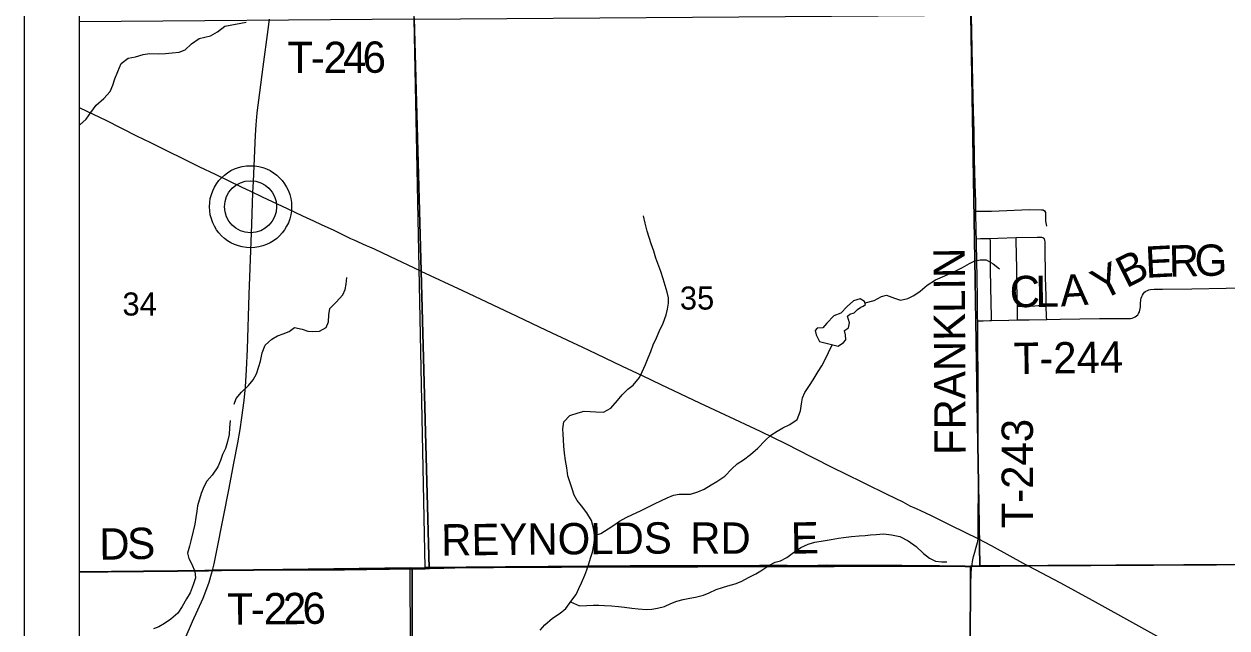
# Model space of a CAD drawing. Extents: x 0 to 70.2, y 0 to 31.4.
# Drawn here: x 2 to 4.18, y 18.211 to 19.306 of the extents above; entities that cross this region are included whole.
import ezdxf

# ---------------------------------------------------------------- set-up
doc = ezdxf.new("R2010")
doc.units = 0
for name, color, linetype in [('GM_X_County_Road', 7, 'Continuous'), ('GM_X_Minor_Lake', 7, 'Continuous'), ('GM_X_Minor_River', 7, 'Continuous'), ('GM_X_Section', 7, 'Continuous'), ('GM_X_Section_Text', 7, 'Continuous'), ('GM_X_State_Route', 7, 'Continuous'), ('GM_X_Township_Road', 7, 'Continuous'), ('GM_X_Township_Road_Text', 7, 'Continuous'), ('GM_X_Unincorporated', 7, 'Continuous'), ('GM_X_Unincorporated_Location', 7, 'Continuous'), ('SH_Cut_Line', 7, 'Continuous'), ('SH_Data', 7, 'Continuous')]:
    doc.layers.add(name, color=color, linetype=linetype)

msp = doc.modelspace()

# ---------------------------------------------------------------- linework, layer by layer
at = {"layer": 'GM_X_County_Road'}
for points in [[(3.7171, 18.3219), (3.7185, 18.3314), (3.7204, 18.3404), (3.7231, 18.35), (3.7241, 18.3535), (3.7279, 18.3656), (3.7285, 18.3683), (3.7289, 18.3723)], [(3.7167, 17.7404), (3.7171, 17.8383), (3.7174, 17.9202), (3.7173, 17.9902), (3.7166, 18.078), (3.7155, 18.164), (3.7152, 18.2197), (3.7156, 18.2754), (3.7156, 18.2911), (3.716, 18.3093), (3.7167, 18.3191), (3.7171, 18.3219)]]:
    msp.add_lwpolyline(points, dxfattribs=at)
at = {"layer": 'GM_X_Minor_Lake'}
for points in [[(3.4749, 18.7219), (3.4851, 18.7283), (3.4893, 18.7336), (3.4886, 18.7427), (3.4864, 18.7503), (3.494, 18.7552), (3.4955, 18.7643), (3.4918, 18.7761), (3.496, 18.7799), (3.5044, 18.7825), (3.5101, 18.7885), (3.5162, 18.7927), (3.5207, 18.7942), (3.5249, 18.7976), (3.523, 18.8029), (3.5151, 18.8075), (3.5029, 18.8041), (3.4915, 18.7939), (3.4797, 18.7815), (3.4675, 18.777), (3.4546, 18.7634), (3.4473, 18.7554), (3.4371, 18.7547), (3.4336, 18.7502), (3.4355, 18.7422), (3.4415, 18.7304)], [(3.4415, 18.7304), (3.4749, 18.7219)]]:
    msp.add_lwpolyline(points, dxfattribs=at)
at = {"layer": 'GM_X_Minor_River'}
for points in [[(2.1, 19.1227), (2.1005, 19.1228), (2.1124, 19.1333), (2.1209, 19.1458), (2.1309, 19.1589), (2.1443, 19.1709), (2.1558, 19.1837), (2.1609, 19.1951), (2.1644, 19.2064), (2.1699, 19.2196), (2.1758, 19.2344), (2.1884, 19.2441), (2.2017, 19.2462), (2.2158, 19.251), (2.2276, 19.2524), (2.2431, 19.2522), (2.2564, 19.2528), (2.2682, 19.2538), (2.2811, 19.2552), (2.2922, 19.2589), (2.3037, 19.2701), (2.3171, 19.2795), (2.3377, 19.2845), (2.3507, 19.292), (2.364, 19.3021)], [(2.364, 19.3021), (2.4024, 19.3094)], [(2.9351, 18.2067), (2.9435, 18.2166), (2.9576, 18.229), (2.9713, 18.2377), (2.9816, 18.2464), (2.9923, 18.2611), (3.0003, 18.2717), (3.0053, 18.2823), (3.0103, 18.2926), (3.0164, 18.3066), (3.0199, 18.3164), (3.0234, 18.3274), (3.0261, 18.3373), (3.0299, 18.3483), (3.0326, 18.3608), (3.0334, 18.3703), (3.0338, 18.3797), (3.0316, 18.3919), (3.0279, 18.4056), (3.02, 18.4197), (3.0102, 18.4322), (3.0023, 18.4421), (2.997, 18.4517), (2.9929, 18.4631), (2.9888, 18.4756), (2.9854, 18.4866), (2.9832, 18.5011), (2.981, 18.5144), (2.9795, 18.528), (2.9781, 18.5406), (2.9774, 18.552), (2.9767, 18.5622), (2.9763, 18.5717), (2.9783, 18.5846), (2.989, 18.596), (3.0038, 18.6012), (3.0152, 18.6038), (3.0258, 18.6034), (3.036, 18.6026), (3.0497, 18.6025), (3.0634, 18.6096), (3.0752, 18.6236), (3.0836, 18.6338), (3.0939, 18.6437), (3.1034, 18.6512), (3.1149, 18.6652), (3.1202, 18.6754), (3.126, 18.6887), (3.131, 18.7008), (3.136, 18.7125), (3.1398, 18.7243), (3.146, 18.7372), (3.151, 18.7485), (3.1579, 18.7633), (3.1636, 18.7784), (3.1659, 18.7887), (3.1675, 18.8001), (3.1676, 18.8096), (3.1653, 18.8198), (3.1616, 18.8316), (3.1579, 18.8438), (3.1537, 18.8571), (3.1481, 18.8715), (3.1448, 18.8814), (3.141, 18.894), (3.1365, 18.9073), (3.1328, 18.9187), (3.1291, 18.9305), (3.1257, 18.9449), (3.1227, 18.9582)], [(3.5238, 18.8006), (3.5401, 18.8047), (3.5534, 18.8119), (3.5629, 18.8141), (3.577, 18.8091), (3.5879, 18.8052), (3.6016, 18.8082), (3.6123, 18.8138), (3.6237, 18.8218), (3.6363, 18.8323), (3.6515, 18.8421), (3.664, 18.8478), (3.6792, 18.8541), (3.6895, 18.859), (3.7002, 18.8647), (3.7131, 18.8718), (3.723, 18.8763), (3.7325, 18.8786), (3.7431, 18.8785), (3.756, 18.8712), (3.7677, 18.8621)], [(2.3805, 18.6167), (2.3843, 18.627), (2.3942, 18.6387), (2.4064, 18.6504), (2.4152, 18.661), (2.421, 18.672), (2.4256, 18.6852), (2.4283, 18.6947), (2.4314, 18.7099), (2.4371, 18.7239), (2.4489, 18.7345), (2.4592, 18.7405), (2.4695, 18.7442), (2.4805, 18.7487), (2.49, 18.7555), (2.5041, 18.7528), (2.5139, 18.749), (2.5234, 18.7485), (2.5352, 18.7492), (2.5473, 18.7556), (2.5515, 18.7662), (2.552, 18.7788), (2.5543, 18.7901), (2.5658, 18.8018), (2.5776, 18.8147), (2.5818, 18.8245), (2.5837, 18.8344), (2.5849, 18.8462)], [(3.0338, 18.3784), (3.0452, 18.382), (3.0586, 18.3906), (3.0685, 18.3974), (3.0791, 18.4046), (3.0913, 18.4114), (3.1023, 18.4166), (3.1168, 18.4234), (3.1301, 18.4298), (3.1434, 18.4365), (3.154, 18.4414), (3.1654, 18.4471), (3.1765, 18.4519), (3.1871, 18.4538), (3.1966, 18.4534), (3.2076, 18.4537), (3.2209, 18.4578), (3.2323, 18.4623), (3.2449, 18.4702), (3.2555, 18.4766), (3.2696, 18.4864), (3.2822, 18.4992), (3.2921, 18.5083), (3.3035, 18.5155), (3.3165, 18.5257), (3.3294, 18.537), (3.3431, 18.551), (3.353, 18.5604), (3.3645, 18.5676), (3.3747, 18.574), (3.3873, 18.58), (3.4006, 18.589), (3.4068, 18.6046), (3.4087, 18.6174), (3.4107, 18.6281), (3.4145, 18.6379), (3.4233, 18.6508), (3.4298, 18.6606), (3.439, 18.6758), (3.4455, 18.6864), (3.4512, 18.6966), (3.4645, 18.7245)], [(2.3736, 18.5873), (2.3723, 18.5737), (2.3714, 18.5619), (2.3686, 18.549), (2.365, 18.5362), (2.3596, 18.5256), (2.3557, 18.5143), (2.351, 18.5029), (2.3406, 18.4878), (2.3313, 18.4769), (2.3255, 18.4671), (2.3208, 18.455), (2.3145, 18.4323), (2.3129, 18.4225), (2.3112, 18.4111), (2.3092, 18.3994), (2.3064, 18.3865), (2.302, 18.3691), (2.2996, 18.3592), (2.2961, 18.3467), (2.2986, 18.3368), (2.3042, 18.3265), (2.3094, 18.3131), (2.3108, 18.3021), (2.3065, 18.2893), (2.301, 18.2745), (2.2944, 18.264), (2.2867, 18.25), (2.2789, 18.2379), (2.2659, 18.2267), (2.2544, 18.2188), (2.2441, 18.2129), (2.2346, 18.2096)], [(2.9903, 18.2584), (3.0067, 18.2508), (3.02, 18.2515), (3.0317, 18.2522), (3.0412, 18.2522), (3.0518, 18.2514), (3.0643, 18.2509), (3.0772, 18.2497), (3.0882, 18.2485), (3.1011, 18.2469), (3.1129, 18.2454), (3.1277, 18.2445), (3.1375, 18.2452), (3.1478, 18.2467), (3.1603, 18.2501), (3.1721, 18.2553), (3.1831, 18.2594), (3.1942, 18.2628), (3.2063, 18.265), (3.2169, 18.2669), (3.2314, 18.2706), (3.2416, 18.2747), (3.2542, 18.2804), (3.2656, 18.2845), (3.2755, 18.2875), (3.2884, 18.2908), (3.2994, 18.2949), (3.3139, 18.3028), (3.3257, 18.3092), (3.3352, 18.3145), (3.3493, 18.3243), (3.3611, 18.3303), (3.3705, 18.3326), (3.3823, 18.3386), (3.3919, 18.3457), (3.4075, 18.3567), (3.4208, 18.3631), (3.4329, 18.3668), (3.4481, 18.369), (3.4622, 18.3712), (3.4755, 18.3738), (3.485, 18.3749), (3.4994, 18.3767), (3.513, 18.3778), (3.5241, 18.3785), (3.5335, 18.3796), (3.5438, 18.3807), (3.5575, 18.3814), (3.5715, 18.3798), (3.5867, 18.3767), (3.6018, 18.369), (3.6165, 18.3587), (3.6298, 18.3461), (3.6407, 18.3377), (3.6517, 18.3323), (3.6627, 18.3311), (3.6722, 18.3311)]]:
    msp.add_lwpolyline(points, dxfattribs=at)
at = {"layer": 'GM_X_Section'}
for points in [[(3.7154, 19.3219), (4.7288, 19.3363), (4.7368, 18.3286), (4.7171, 18.3286), (3.7317, 18.3233)], [(2.7066, 19.3148), (3.7154, 19.3219), (3.7317, 18.3233), (3.715, 18.323), (2.7267, 18.3203)], [(3.715, 18.323), (3.7116, 17.3342), (2.7039, 17.3191), (2.6994, 18.3199), (2.7267, 18.3203)], [(4.7171, 18.3286), (4.7109, 17.3315), (3.7116, 17.3342), (3.715, 18.323), (3.7317, 18.3233)]]:
    msp.add_lwpolyline(points, close=True, dxfattribs=at)
at = {"layer": 'GM_X_Section_Text'}
for points in [[(2.1, 20.9), (2.1, 18.3126), (2.2164, 18.3137), (2.2784, 18.3145), (2.3277, 18.3152), (2.3343, 18.3153), (2.3412, 18.3156), (2.3574, 18.3156), (2.4158, 18.3166), (2.4655, 18.3166), (2.5245, 18.3166), (2.5804, 18.317), (2.6618, 18.318), (2.7031, 18.3186), (2.7265, 18.319), (2.7342, 18.3192), (2.7194, 18.8581), (2.7067, 19.3173), (2.6915, 19.8217), (2.6758, 20.3443), (2.6527, 20.8458)], [(2.7067, 19.3173), (2.7194, 18.8581), (2.7342, 18.3192), (2.7604, 18.3199), (2.8009, 18.3209), (2.8505, 18.3211), (2.8722, 18.3216), (2.9498, 18.3224), (3.0208, 18.3229), (3.0366, 18.3228), (3.0423, 18.3228), (3.0695, 18.3229), (3.0981, 18.3235), (3.1356, 18.3233), (3.1566, 18.3235), (3.1972, 18.3233), (3.2277, 18.3234), (3.2494, 18.3233), (3.3018, 18.3235), (3.3328, 18.3239), (3.3483, 18.3241), (3.3825, 18.3241), (3.4228, 18.3238), (3.4538, 18.3245), (3.5127, 18.3244), (3.5904, 18.3243), (3.6587, 18.3235), (3.7052, 18.3227), (3.7169, 18.3225), (3.8196, 18.3236), (4.729, 18.3286)], [(2.7027, 17.7825), (2.7031, 18.3186), (2.6618, 18.318), (2.5804, 18.317), (2.5245, 18.3166), (2.4655, 18.3166), (2.4158, 18.3166), (2.3574, 18.3156), (2.3412, 18.3156), (2.3343, 18.3153), (2.3277, 18.3152), (2.2784, 18.3145), (2.2164, 18.3137), (2.1, 18.3126), (2.1, 14.1)], [(4.729, 18.3286), (3.8196, 18.3236), (3.7169, 18.3225), (3.7052, 18.3227), (3.6587, 18.3235), (3.5904, 18.3243), (3.5127, 18.3244), (3.4538, 18.3245), (3.4228, 18.3238), (3.3825, 18.3241), (3.3483, 18.3241), (3.3328, 18.3239), (3.3018, 18.3235), (3.2494, 18.3233), (3.2277, 18.3234), (3.1972, 18.3233), (3.1566, 18.3235), (3.1356, 18.3233), (3.0981, 18.3235), (3.0695, 18.3229), (3.0423, 18.3228), (3.0366, 18.3228), (3.0208, 18.3229), (2.9498, 18.3224), (2.8722, 18.3216), (2.8505, 18.3211), (2.8009, 18.3209), (2.7604, 18.3199), (2.7342, 18.3192), (2.7265, 18.319), (2.7031, 18.3186), (2.7027, 17.7825)]]:
    msp.add_lwpolyline(points, dxfattribs=at)
at = {"layer": 'GM_X_State_Route'}
msp.add_line((2.7187, 18.8579), (2.6628, 18.8844), dxfattribs=at)
for points in [[(2.1, 19.3098), (2.1, 18.3121), (2.6994, 18.3199), (2.7267, 18.3203), (2.7066, 19.3148)], [(2.1, 18.3121), (2.1, 17.3126), (2.7039, 17.3191), (2.6994, 18.3199)]]:
    msp.add_lwpolyline(points, close=True, dxfattribs=at)
for points in [[(2.3414, 18.3151), (2.3443, 18.327), (2.3495, 18.3513), (2.3715, 18.4642), (2.3803, 18.51), (2.3875, 18.5465), (2.3918, 18.571), (2.3949, 18.5925), (2.3986, 18.6233), (2.401, 18.6481), (2.403, 18.6791), (2.4048, 18.7163), (2.408, 18.8157), (2.4127, 18.943), (2.4148, 19.0005), (2.4155, 19.0207), (2.4191, 19.1045), (2.4204, 19.1232), (2.4226, 19.1448), (2.4273, 19.1819), (2.4334, 19.2281), (2.4422, 19.2959), (2.4446, 19.3145)], [(2.4148, 19.0005), (2.4111, 19.0023), (2.3941, 19.0101), (2.3467, 19.0334), (2.3187, 19.0465), (2.2296, 19.0905), (2.2045, 19.1029), (2.149, 19.1308), (2.1014, 19.1535), (2.1, 19.1542)], [(2.6628, 18.8844), (2.6349, 18.8977), (2.6263, 18.9014), (2.6205, 18.9037), (2.5979, 18.9139), (2.5923, 18.9165), (2.5894, 18.9176), (2.5617, 18.9315), (2.5392, 18.942), (2.525, 18.9483), (2.5053, 18.9574), (2.4774, 18.971), (2.4323, 18.992), (2.4273, 18.9944), (2.4148, 19.0005)], [(3.8198, 18.323), (3.8154, 18.3254), (3.7527, 18.3597), (3.7289, 18.3723), (3.6807, 18.3962), (3.6444, 18.4141), (3.625, 18.4235), (3.617, 18.427), (3.6056, 18.4319), (3.593, 18.4388), (3.5791, 18.4454), (3.5627, 18.4537), (3.5258, 18.4714), (3.4845, 18.4923), (3.4704, 18.4989), (3.4261, 18.5215), (3.3818, 18.544), (3.3343, 18.567), (3.2697, 18.5974), (3.2245, 18.6183), (3.1545, 18.652), (3.1208, 18.6678), (3.0843, 18.685), (3.0226, 18.7144), (2.9466, 18.7501), (2.8934, 18.7756), (2.7951, 18.8221), (2.7196, 18.8575), (2.7187, 18.8579)], [(2.1376, 17.7864), (2.1446, 17.816), (2.1475, 17.8283), (2.154, 17.8555), (2.1597, 17.8797), (2.1663, 17.9037), (2.1727, 17.9246), (2.1798, 17.9452), (2.1864, 17.9626), (2.1936, 17.9799), (2.2069, 18.008), (2.2359, 18.0665), (2.2491, 18.0946), (2.2669, 18.1343), (2.3055, 18.2225), (2.3243, 18.2652), (2.3314, 18.2824), (2.3355, 18.2941), (2.3399, 18.3089), (2.3414, 18.3151)], [(4.0962, 18.1719), (3.9876, 18.2324), (3.9359, 18.2608), (3.8785, 18.2919), (3.8198, 18.323)]]:
    msp.add_lwpolyline(points, dxfattribs=at)
at = {"layer": 'GM_X_Township_Road'}
msp.add_line((2.1, 18.3121), (2.2036, 18.3131), dxfattribs=at)
for points in [[(3.7259, 18.9166), (3.7255, 18.9286), (3.7249, 18.9667), (3.7245, 18.984), (3.7235, 19.015), (3.7223, 19.0616), (3.7213, 19.1113), (3.7205, 19.1486), (3.7192, 19.2014), (3.7168, 19.3213)], [(3.7249, 18.9667), (3.7343, 18.9665), (3.7531, 18.9669), (3.8219, 18.9696), (3.8437, 18.9693), (3.8468, 18.9688), (3.8492, 18.967), (3.8506, 18.9643), (3.8509, 18.9612), (3.8508, 18.9518), (3.8511, 18.9487), (3.8523, 18.9425), (3.8527, 18.9394)], [(3.7259, 18.9166), (3.7332, 18.9168), (3.7508, 18.9173), (3.7643, 18.9177), (3.7977, 18.9186), (3.8356, 18.9196), (3.8435, 18.9195), (3.8452, 18.919), (3.846, 18.9187), (3.8469, 18.9182), (3.8477, 18.9176), (3.8485, 18.9167)], [(3.728, 18.7681), (3.7276, 18.7737), (3.7274, 18.8099), (3.7266, 18.8783), (3.7261, 18.9063), (3.7259, 18.9166)], [(3.7531, 18.7683), (3.7529, 18.7754), (3.7524, 18.8003), (3.7514, 18.8595), (3.7509, 18.9125), (3.7508, 18.9173)], [(3.7999, 18.7694), (3.8, 18.7752), (3.8001, 18.7815), (3.7998, 18.7945), (3.799, 18.8346), (3.7988, 18.8628), (3.7978, 18.9127), (3.7977, 18.9186)], [(3.853, 18.7705), (3.8529, 18.7742), (3.8521, 18.7956), (3.852, 18.8131), (3.851, 18.8464), (3.8505, 18.9023), (3.85, 18.9107), (3.8497, 18.9141), (3.8485, 18.9167)], [(3.7531, 18.7683), (3.7842, 18.7691), (3.7999, 18.7694), (3.8214, 18.7699), (3.853, 18.7705), (3.8772, 18.771), (3.9486, 18.772), (3.9859, 18.772), (4.0014, 18.7719), (4.0046, 18.7722), (4.0076, 18.7727), (4.0106, 18.7736), (4.0133, 18.7749), (4.0158, 18.7766), (4.0179, 18.7788), (4.0196, 18.7813), (4.0209, 18.7841), (4.0218, 18.7871), (4.0224, 18.7902), (4.0227, 18.7933), (4.0232, 18.7995), (4.0238, 18.8057), (4.0244, 18.8087), (4.0253, 18.8117), (4.0266, 18.8145), (4.0282, 18.8172), (4.0302, 18.8195), (4.0327, 18.8215), (4.0354, 18.8229), (4.0383, 18.8239), (4.0413, 18.8245), (4.0475, 18.825), (4.0631, 18.8251), (4.1158, 18.8256), (4.1779, 18.8271), (4.2741, 18.8282)], [(3.7998, 18.7945), (3.8069, 18.7947), (3.8313, 18.7953), (3.8373, 18.7954), (3.8521, 18.7956)], [(3.728, 18.7681), (3.7376, 18.7681), (3.75, 18.7682), (3.7531, 18.7683)], [(3.7289, 18.3723), (3.7286, 18.3791), (3.7288, 18.3903), (3.7293, 18.4835), (3.729, 18.555), (3.7289, 18.6514), (3.7281, 18.7384), (3.7282, 18.7595), (3.728, 18.7681)], [(2.2036, 18.3131), (2.2166, 18.3132), (2.2786, 18.3139), (2.3279, 18.3147), (2.3345, 18.3148), (2.3414, 18.3151)], [(2.3414, 18.3151), (2.3576, 18.315), (2.416, 18.316), (2.4657, 18.3161), (2.5247, 18.3161), (2.5806, 18.3165), (2.662, 18.3175), (2.7033, 18.3181)], [(2.7033, 18.3181), (2.7268, 18.3184), (2.7345, 18.3187)], [(2.7345, 18.3187), (2.7606, 18.3194), (2.8011, 18.3203), (2.8507, 18.3205), (2.8724, 18.3211), (2.95, 18.3219), (3.021, 18.3224), (3.0368, 18.3223), (3.0425, 18.3223), (3.0698, 18.3224), (3.0983, 18.323), (3.1358, 18.3228), (3.1569, 18.323), (3.1974, 18.3228), (3.2279, 18.3228), (3.2496, 18.3228), (3.302, 18.3229), (3.333, 18.3233), (3.3485, 18.3235), (3.3827, 18.3235), (3.4231, 18.3233), (3.454, 18.324), (3.513, 18.3239), (3.5906, 18.3237), (3.6589, 18.323), (3.7055, 18.3221), (3.7171, 18.3219)]]:
    msp.add_lwpolyline(points, dxfattribs=at)
at = {"layer": 'GM_X_Unincorporated'}
for radius in [0.0744, 0.0472]:
    msp.add_circle((2.4104, 18.9747), radius, dxfattribs=at)
at = {"layer": 'GM_X_Unincorporated_Location'}
msp.add_line((2.4104, 18.9747), (2.4104, 18.9747), dxfattribs=at)
at = {"layer": 'SH_Cut_Line'}
msp.add_lwpolyline([(6.7786, 18.1369), (6.7742, 18.3058), (6.7461, 18.306), (6.749, 19.3206), (6.7395, 20.3365), (6.7343, 20.9), (2.1, 20.9), (2.1, 14.1)], dxfattribs=at)
at = {"layer": 'SH_Data'}
for p, q in [((2, 21), (2, 14)), ((2.1, 20.9), (2.1, 14.1))]:
    msp.add_line(p, q, dxfattribs=at)

# ---------------------------------------------------------------- texts
at = {"layer": 'GM_X_Section_Text'}
for s, p in [('34', (2.1783, 18.7774)), ('35', (3.1883, 18.7882))]:
    msp.add_text(s, height=0.04186, rotation=0, dxfattribs=at).set_placement(p)
at = {"layer": 'GM_X_Township_Road_Text'}
for s, height, rotation, p in [('T', 0.0568, 0, (2.477, 19.217)), ('2', 0.0568, 0.0477, (2.5429, 19.217)), ('4', 0.0568, 0.2057, (2.5781, 19.2171)), ('6', 0.0568, 0.9562, (2.6139, 19.2172)), ('-', 0.0568, 0.0086, (2.5195, 19.217)), ('E', 0.0568, 2.8382, (4.0329, 18.8457)), ('R', 0.0568, 1.1554, (4.0749, 18.8478)), ('G', 0.0568, 1.1257, (4.1216, 18.8488)), ('FRANKLIN', 0.05682, 90.2691, (3.7063, 18.5247)), ('Y', 0.0568, 27.0952, (3.9528, 18.8037)), ('B', 0.0568, 26.5912, (3.9972, 18.8264)), ('C', 0.0568, 0.8782, (3.7864, 18.7922)), ('L', 0.0568, 0.8791, (3.8331, 18.7929)), ('A', 0.0568, 3.8511, (3.8788, 18.7937)), ('T-244', 0.05682, 0.8211, (3.7936, 18.6712)), ('T-243', 0.05682, 90, (3.8281, 18.3915)), ('REYNOLDS', 0.05682, 0.5128, (2.756, 18.3422)), ('RD', 0.05682, 0, (3.207, 18.3455)), ('E', 0.0568, 0.9428, (3.3898, 18.3455)), ('D', 0.0568, 0.6796, (2.1366, 18.3346)), ('S', 0.0568, 1.5237, (2.1876, 18.3352)), ('T', 0.0568, 0.3043, (2.3684, 18.217)), ('2', 0.0568, 0.3569, (2.4343, 18.2174)), ('2', 0.0568, 0.51, (2.4694, 18.2176)), ('6', 0.0568, 1.253, (2.5052, 18.2179)), ('-', 0.0568, 0.3148, (2.4109, 18.2173))]:
    msp.add_text(s, height=height, rotation=rotation, dxfattribs=at).set_placement(p)

doc.saveas('drawing.dxf')
